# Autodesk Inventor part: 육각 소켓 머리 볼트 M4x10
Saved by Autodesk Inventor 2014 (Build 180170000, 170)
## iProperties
Created: 2025-06
Part Number: 육각 소켓 머리 볼트 M4x10
Material: 강철, 연강
Document SubType Name: Modeling
Designer: dg
Density: 7.86 g/cm^3
Appearance: 강철
Mass: 2.0371 g
Surface Area: 3.0572 cm^2
Volume: 0.259174 cm^3
Author: jhkim
Description: 6각머리 태핑 나사
Creation Date: 2025-05-27
Sending System: Autodesk Inventor 2026
Preprocessor: ST-DEVELOPER v20.1
Author: dg
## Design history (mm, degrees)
node "육각 소켓 머리 볼트 M4x101"
body "Solid1"
node "기준1"
